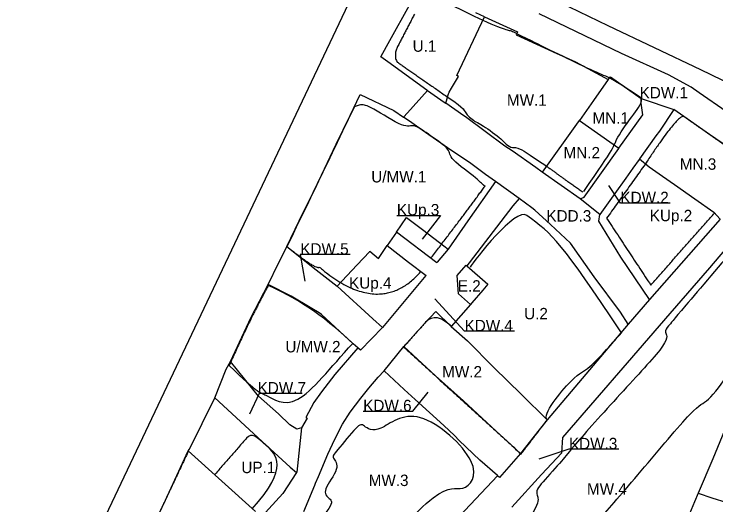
# Model space of a CAD drawing. Extents: x 7424788 to 7425732, y 5549810 to 5550591.
# Drawn here: x 7425037.8 to 7425283.7, y 5550276.4 to 5550448.5 of the extents above; entities that cross this region are included whole.
import ezdxf

# ---------------------------------------------------------------- set-up
doc = ezdxf.new("R2010")
doc.units = 0
for name, color, linetype in [('WIL_granica obszaru objętego planem', 7, 'Continuous'), ('WIL_linia rozgraniczające tereny o różnym przeznaczeniu lub różnych zasadach zagospodarowania', 7, 'Continuous'), ('WIL_linia rozgraniczające tereny o różnym przeznaczeniu lub różnych zasadach zagospodarowania_OPISY', 7, 'Continuous'), ('WIL_nieprzekraczalne linie zabudowy', 7, 'Continuous')]:
    doc.layers.add(name, color=color, linetype=linetype)

msp = doc.modelspace()

# ---------------------------------------------------------------- linework, layer by layer
at = {"layer": 'WIL_granica obszaru objętego planem'}
msp.add_line((7424904.13, 5549923.06), (7425177.26, 5550499.06), dxfattribs=at)
at = {"layer": 'WIL_linia rozgraniczające tereny o różnym przeznaczeniu lub różnych zasadach zagospodarowania'}
for p, q in [((7424904.13, 5549923.06), (7425177.26, 5550499.06)), ((7425207.99, 5550462.87), (7425245.88, 5550444.53)), ((7425168.28, 5550437.16), (7425177.56, 5550453.84)), ((7425192.92, 5550426.96), (7425202.6, 5550447.56)), ((7425202.6, 5550447.56), (7425199.62, 5550448.89)), ((7425202.6, 5550447.56), (7425214.19, 5550442.28)), ((7425250.66, 5550434.71), (7425221.8, 5550448.54)), ((7425245.88, 5550444.53), (7425278.31, 5550429.04)), ((7425214.19, 5550442.28), (7425213.71, 5550441.25)), ((7425213.71, 5550441.25), (7425227.98, 5550434.72)), ((7425166.26, 5550433.54), (7425168.28, 5550437.16)), ((7425168.74, 5550431.75), (7425166.26, 5550433.54)), ((7425227.98, 5550434.72), (7425230.92, 5550433.39)), ((7425230.92, 5550433.39), (7425234.46, 5550431.78)), ((7425267.09, 5550427.17), (7425250.66, 5550434.71)), ((7425182.4, 5550421.84), (7425168.74, 5550431.75)), ((7425234.46, 5550431.78), (7425245.94, 5550425.55)), ((7425278.31, 5550429.04), (7425324.29, 5550406.7)), ((7425191.09, 5550422.52), (7425193.55, 5550426.58)), ((7425193.55, 5550426.58), (7425192.92, 5550426.96)), ((7425245.94, 5550425.55), (7425240.78, 5550418.23)), ((7425245.94, 5550425.55), (7425246.71, 5550426.54)), ((7425246.71, 5550426.54), (7425257.54, 5550418.86)), ((7425275, 5550422.9), (7425267.09, 5550427.17)), ((7425175.64, 5550413.93), (7425182.63, 5550421.68)), ((7425182.63, 5550421.68), (7425182.4, 5550421.84)), ((7425182.63, 5550421.68), (7425188.49, 5550417.61)), ((7425189.93, 5550420.15), (7425190.22, 5550421.08)), ((7425190.22, 5550421.08), (7425191.09, 5550422.52)), ((7425277.85, 5550420.91), (7425275, 5550422.9)), ((7425287.26, 5550414.34), (7425277.85, 5550420.91)), ((7425155.57, 5550412.91), (7425159.06, 5550420.34)), ((7425159.06, 5550420.34), (7425170.83, 5550414.69)), ((7425189.06, 5550417.22), (7425189.93, 5550420.15)), ((7425240.78, 5550418.23), (7425239.94, 5550417.03)), ((7425257.47, 5550417.23), (7425257.54, 5550418.86)), ((7425257.54, 5550418.86), (7425268.97, 5550415.01)), ((7425188.49, 5550417.61), (7425189.06, 5550417.22)), ((7425195.43, 5550412.8), (7425189.06, 5550417.22)), ((7425239.94, 5550417.03), (7425235.87, 5550411.24)), ((7425258.1, 5550413.19), (7425257.47, 5550417.23)), ((7425170.83, 5550414.69), (7425174.21, 5550412.34)), ((7425174.26, 5550412.31), (7425175.64, 5550413.93)), ((7425249.74, 5550401.45), (7425258.1, 5550413.19)), ((7425268.97, 5550415.01), (7425263.91, 5550407.46)), ((7425272.45, 5550412.59), (7425268.97, 5550415.01)), ((7425150.71, 5550402.86), (7425155.57, 5550412.91)), ((7425174.21, 5550412.34), (7425174.26, 5550412.31)), ((7425177.12, 5550410.32), (7425174.26, 5550412.31)), ((7425195.92, 5550412.44), (7425195.43, 5550412.8)), ((7425209.76, 5550402.2), (7425195.92, 5550412.44)), ((7425235.48, 5550410.76), (7425222.82, 5550393.09)), ((7425235.82, 5550411.17), (7425235.48, 5550410.76)), ((7425235.87, 5550411.24), (7425235.82, 5550411.17)), ((7425235.87, 5550411.24), (7425249.74, 5550401.45)), ((7425281.41, 5550406.3), (7425272.45, 5550412.59)), ((7425179.62, 5550408.63), (7425177.12, 5550410.32)), ((7425183.09, 5550406.13), (7425179.62, 5550408.63)), ((7425191.17, 5550400.58), (7425183.09, 5550406.13)), ((7425262.66, 5550405.83), (7425256.92, 5550397.75)), ((7425263.91, 5550407.46), (7425262.66, 5550405.83)), ((7425288.42, 5550401.48), (7425281.41, 5550406.3)), ((7425145.51, 5550392.02), (7425150.71, 5550402.86)), ((7425212.34, 5550400.51), (7425209.76, 5550402.2)), ((7425237.56, 5550384.37), (7425249.69, 5550401.37)), ((7425249.69, 5550401.37), (7425249.74, 5550401.45)), ((7425197.31, 5550396.45), (7425191.17, 5550400.58)), ((7425220.56, 5550394.69), (7425212.34, 5550400.51)), ((7425203.03, 5550392.29), (7425197.31, 5550396.45)), ((7425256.76, 5550397.52), (7425254.59, 5550394.46)), ((7425256.92, 5550397.75), (7425256.76, 5550397.52)), ((7425256.92, 5550397.75), (7425260.32, 5550395)), ((7425222.82, 5550393.09), (7425220.56, 5550394.69)), ((7425254.59, 5550394.46), (7425252.13, 5550390.99)), ((7425260.32, 5550395), (7425265.01, 5550391.69)), ((7425141.19, 5550383.01), (7425145.51, 5550392.02)), ((7425206.42, 5550389.85), (7425203.03, 5550392.29)), ((7425236.11, 5550383.72), (7425222.82, 5550393.09)), ((7425252.13, 5550390.99), (7425248.31, 5550385.61)), ((7425265.01, 5550391.69), (7425269.21, 5550388.74)), ((7425206.42, 5550389.85), (7425196.79, 5550376.03)), ((7425214.71, 5550383.8), (7425206.42, 5550389.85)), ((7425269.21, 5550388.74), (7425276.33, 5550383.73)), ((7425214.71, 5550383.8), (7425212.6, 5550381.24)), ((7425219.17, 5550380.54), (7425214.71, 5550383.8)), ((7425236.11, 5550383.72), (7425237.56, 5550384.37)), ((7425243.07, 5550378.23), (7425236.11, 5550383.72)), ((7425248.31, 5550385.61), (7425243.07, 5550378.23)), ((7425276.33, 5550383.73), (7425283, 5550379.03)), ((7425139.07, 5550378.94), (7425141.19, 5550383.01)), ((7425212.6, 5550381.24), (7425197.25, 5550361.32)), ((7425133.43, 5550367.01), (7425139.07, 5550378.94)), ((7425220.26, 5550379.78), (7425219.17, 5550380.54)), ((7425225.71, 5550374.68), (7425220.26, 5550379.78)), ((7425283, 5550379.03), (7425285.18, 5550376.64)), ((7425171.76, 5550372.04), (7425175.27, 5550377.23)), ((7425175.27, 5550377.23), (7425180.86, 5550372.98)), ((7425242.68, 5550375.86), (7425243.07, 5550378.23)), ((7425285.18, 5550376.64), (7425260.42, 5550348.39)), ((7425196.79, 5550376.03), (7425189.88, 5550366.12)), ((7425232.71, 5550368.14), (7425225.71, 5550374.68)), ((7425249.13, 5550365.42), (7425242.68, 5550375.86)), ((7425171.76, 5550372.04), (7425168.58, 5550367.37)), ((7425185.87, 5550361.32), (7425171.76, 5550372.04)), ((7425180.86, 5550372.98), (7425186.9, 5550368.4)), ((7425128.69, 5550357.51), (7425133.43, 5550367.01)), ((7425133.43, 5550367.01), (7425143.67, 5550358.85)), ((7425165.48, 5550362.78), (7425168.58, 5550367.37)), ((7425168.58, 5550367.37), (7425175.96, 5550361.54)), ((7425186.9, 5550368.4), (7425189.88, 5550366.12)), ((7425241.01, 5550356.38), (7425232.71, 5550368.14)), ((7425281.55, 5550359.6), (7425288.84, 5550368.05)), ((7425157.85, 5550360.43), (7425162.4, 5550365.33)), ((7425162.4, 5550365.33), (7425162.42, 5550365.34)), ((7425162.42, 5550365.34), (7425165.48, 5550362.78)), ((7425189.88, 5550366.12), (7425186.05, 5550361.53)), ((7425250.42, 5550363.33), (7425249.13, 5550365.42)), ((7425175.96, 5550361.54), (7425182.15, 5550356.86)), ((7425186.05, 5550361.53), (7425185.87, 5550361.32)), ((7425260.42, 5550348.39), (7425250.42, 5550363.33)), ((7425150.99, 5550353.08), (7425157.85, 5550360.43)), ((7425193.04, 5550356.91), (7425196.17, 5550360.49)), ((7425196.17, 5550360.49), (7425196.4, 5550360.29)), ((7425197.25, 5550361.32), (7425196.4, 5550360.29)), ((7425196.4, 5550360.29), (7425203.84, 5550353.77)), ((7425267.7, 5550343.56), (7425281.55, 5550359.6)), ((7425126.86, 5550353.73), (7425128.6, 5550357.34)), ((7425128.6, 5550357.34), (7425128.69, 5550357.51)), ((7425143.67, 5550358.85), (7425150.99, 5550353.08)), ((7425182.12, 5550356.82), (7425166.93, 5550338.62)), ((7425182.15, 5550356.86), (7425182.12, 5550356.82)), ((7425193.47, 5550350.41), (7425193.04, 5550356.91)), ((7425250.32, 5550344), (7425241.01, 5550356.38)), ((7425120.75, 5550342.02), (7425126.86, 5550353.73)), ((7425134.94, 5550349.6), (7425126.86, 5550353.73)), ((7425163.52, 5550341.65), (7425150.99, 5550353.08)), ((7425202.09, 5550351.77), (7425198.14, 5550347.25)), ((7425203.84, 5550353.77), (7425202.09, 5550351.77)), ((7425141.58, 5550345.61), (7425134.94, 5550349.6)), ((7425197.69, 5550346.72), (7425193.47, 5550350.41)), ((7425198.14, 5550347.25), (7425197.69, 5550346.72)), ((7425260.42, 5550348.39), (7425252.9, 5550339.81)), ((7425144.66, 5550343.8), (7425141.58, 5550345.61)), ((7425181.86, 5550340.23), (7425185.58, 5550344.28)), ((7425185.58, 5550344.28), (7425190.96, 5550339.03)), ((7425197.69, 5550346.72), (7425190.96, 5550339.03)), ((7425119.22, 5550338.8), (7425120.75, 5550342.02)), ((7425145.46, 5550343.14), (7425144.66, 5550343.8)), ((7425156.59, 5550332.92), (7425145.46, 5550343.14)), ((7425252.9, 5550339.81), (7425250.32, 5550344)), ((7425252.75, 5550326.27), (7425267.7, 5550343.56)), ((7425166.93, 5550338.62), (7425163.52, 5550341.65)), ((7425174.35, 5550332.02), (7425181.86, 5550340.23)), ((7425252.9, 5550339.81), (7425224.56, 5550306.25)), ((7425113.64, 5550326.7), (7425119.22, 5550338.8)), ((7425166.93, 5550338.62), (7425159.18, 5550330.66)), ((7425190.96, 5550339.03), (7425196.62, 5550333.94)), ((7425158.25, 5550331.47), (7425156.59, 5550332.92)), ((7425167.43, 5550323.42), (7425174.35, 5550332.02)), ((7425174.35, 5550332.02), (7425185.48, 5550321.66)), ((7425196.62, 5550333.94), (7425205.84, 5550324.64)), ((7425158.25, 5550331.47), (7425150.17, 5550322.1)), ((7425159.18, 5550330.66), (7425158.25, 5550331.47)), ((7425112.07, 5550324.05), (7425113.64, 5550326.7)), ((7425123.43, 5550314.57), (7425113.64, 5550326.7)), ((7425205.84, 5550324.64), (7425215.55, 5550315.2)), ((7425230.09, 5550300.05), (7425252.75, 5550326.27)), ((7425108.12, 5550313.95), (7425112.07, 5550324.05)), ((7425165.41, 5550321.19), (7425167.43, 5550323.42)), ((7425174.51, 5550316.93), (7425167.43, 5550323.42)), ((7425150.17, 5550322.1), (7425145.52, 5550316.1)), ((7425162.15, 5550317.33), (7425165.41, 5550321.19)), ((7425185.48, 5550321.66), (7425195.21, 5550312.87)), ((7425159.27, 5550313.83), (7425162.15, 5550317.33)), ((7425145.52, 5550316.1), (7425142.81, 5550312.33)), ((7425178.33, 5550313.44), (7425174.51, 5550316.93)), ((7425215.55, 5550315.2), (7425224.56, 5550306.25)), ((7425099.24, 5550296.01), (7425108.12, 5550313.95)), ((7425108.12, 5550313.95), (7425124.71, 5550298.71)), ((7425130.5, 5550308.36), (7425123.43, 5550314.57)), ((7425142.81, 5550312.33), (7425140.04, 5550307.1)), ((7425155.55, 5550308.93), (7425159.27, 5550313.83)), ((7425188.35, 5550304.25), (7425178.33, 5550313.44)), ((7425195.21, 5550312.87), (7425205.05, 5550303.83)), ((7425134.45, 5550304.57), (7425130.5, 5550308.36)), ((7425152.9, 5550304.8), (7425155.55, 5550308.93)), ((7425140.47, 5550306.85), (7425138.53, 5550303.47)), ((7425140.04, 5550307.1), (7425140.47, 5550306.85)), ((7425224.56, 5550306.25), (7425221.76, 5550302.72)), ((7425136.88, 5550302.96), (7425134.45, 5550304.57)), ((7425138.53, 5550303.47), (7425136.84, 5550287.89)), ((7425138.53, 5550303.47), (7425136.88, 5550302.96)), ((7425150.14, 5550299.52), (7425152.9, 5550304.8)), ((7425192.06, 5550300.72), (7425188.35, 5550304.25)), ((7425205.05, 5550303.83), (7425209.68, 5550299.56)), ((7425221.76, 5550302.72), (7425215.19, 5550294.45)), ((7425286.73, 5550302.51), (7425282.57, 5550292.54)), ((7425193.78, 5550299.08), (7425192.06, 5550300.72)), ((7425229.67, 5550294.69), (7425230.09, 5550300.05)), ((7425124.71, 5550298.71), (7425134.5, 5550289.66)), ((7425147.78, 5550294.2), (7425150.14, 5550299.52)), ((7425200.99, 5550292.1), (7425193.78, 5550299.08)), ((7425209.68, 5550299.56), (7425215.19, 5550294.45)), ((7425090.81, 5550278.06), (7425098.81, 5550295.36)), ((7425098.81, 5550295.36), (7425099.24, 5550296.01)), ((7425098.81, 5550295.36), (7425122.45, 5550274.11)), ((7425144.45, 5550286.46), (7425147.78, 5550294.2)), ((7425215.19, 5550294.45), (7425207.92, 5550286.01)), ((7425222.6, 5550287.16), (7425229.67, 5550294.69)), ((7425207.12, 5550286.71), (7425200.99, 5550292.1)), ((7425282.57, 5550292.54), (7425277.49, 5550280.55)), ((7425136.76, 5550287.77), (7425131.92, 5550280.39)), ((7425134.5, 5550289.66), (7425136.76, 5550287.77)), ((7425136.84, 5550287.89), (7425136.76, 5550287.77)), ((7425143.45, 5550284.02), (7425144.45, 5550286.46)), ((7425207.15, 5550286.68), (7425193.88, 5550272.5)), ((7425207.15, 5550286.68), (7425207.12, 5550286.71)), ((7425207.92, 5550286.01), (7425207.15, 5550286.68)), ((7425212.23, 5550275.61), (7425222.6, 5550287.16)), ((7425139.33, 5550274.15), (7425143.17, 5550283.36)), ((7425143.17, 5550283.36), (7425143.45, 5550284.02)), ((7425131.92, 5550280.39), (7425124.63, 5550272.37)), ((7425277.49, 5550280.55), (7425276.2, 5550277.52)), ((7425277.49, 5550280.55), (7425282.27, 5550278.94)), ((7425085.37, 5550266.74), (7425090.81, 5550278.06)), ((7425282.27, 5550278.94), (7425287.49, 5550277.24)), ((7425276.2, 5550277.52), (7425268.06, 5550258.13))]:
    msp.add_line(p, q, dxfattribs=at)
at = {"layer": 'WIL_linia rozgraniczające tereny o różnym przeznaczeniu lub różnych zasadach zagospodarowania_OPISY'}
for points in [[(7425267.64, 5550382.21), (7425250.23, 5550382.21), (7425246.21, 5550388.41)], [(7425171.92, 5550377.92), (7425187.2, 5550377.92), (7425180.73, 5550369.54)], [(7425155.56, 5550364.18), (7425138.09, 5550364.18), (7425139.72, 5550354.93)], [(7425213.08, 5550337.32), (7425195.65, 5550337.32), (7425185.2, 5550348.68)], [(7425138.78, 5550315.5), (7425123.63, 5550315.5), (7425120.3, 5550308.29)], [(7425160.13, 5550309.29), (7425177.57, 5550309.29), (7425182.92, 5550315.91)], [(7425249.66, 5550295.96), (7425232.21, 5550295.96), (7425221.61, 5550292.45)]]:
    msp.add_lwpolyline(points, dxfattribs=at)
at = {"layer": 'WIL_nieprzekraczalne linie zabudowy'}
for points, degree in [([(7425257.76, 5550418.9), (7425246.92, 5550426.31), (7425245.99, 5550425.78), (7425214.11, 5550441.52), (7425211.86, 5550442.72), (7425208.96, 5550443.12), (7425195.85, 5550449.07), (7425186.99, 5550453.7), (7425182.09, 5550455.88)], 3), ([(7425178.1, 5550448.49), (7425171.99, 5550436.77)], 1), ([(7425171.99, 5550436.77), (7425171.41, 5550435.31), (7425171.37, 5550434.23), (7425171.41, 5550433.26), (7425171.53, 5550432.5), (7425172.05, 5550431.69)], 3), ([(7425172.05, 5550431.69), (7425178.37, 5550427.26), (7425189.88, 5550419.3)], 2), ([(7425189.88, 5550419.3), (7425195.94, 5550415.21), (7425195.26, 5550413.81), (7425200.29, 5550410.1), (7425200.94, 5550410.39), (7425209.89, 5550403.69), (7425209.67, 5550403.11), (7425212.73, 5550401.15), (7425213.89, 5550402.53), (7425221.68, 5550396.93), (7425224.5, 5550395.11)], 3), ([(7425237.39, 5550386.36), (7425248.5, 5550402.1), (7425247.45, 5550403.03), (7425254.72, 5550413.35), (7425257.5, 5550416.65), (7425257.76, 5550418.9)], 3), ([(7425156.93, 5550415.88), (7425145.59, 5550392.09), (7425139.01, 5550378.64), (7425133.43, 5550367.01)], 3), ([(7425156.95, 5550415.88), (7425156.93, 5550415.88)], 1), ([(7425202.88, 5550388.06), (7425201.17, 5550389.35), (7425201.48, 5550389.89), (7425189.59, 5550398.24), (7425191.23, 5550400.67), (7425183.66, 5550405.84), (7425177.18, 5550410.5), (7425175.51, 5550407.81), (7425162.12, 5550416.54), (7425159.35, 5550416.83), (7425158.04, 5550416.39), (7425156.94, 5550415.92), (7425156.95, 5550415.88)], 3), ([(7425272.45, 5550412.55), (7425270.76, 5550413.8), (7425259.29, 5550396.41)], 2), ([(7425299.17, 5550393.9), (7425272.45, 5550412.55)], 1), ([(7425259.29, 5550396.41), (7425245.42, 5550376.93)], 1), ([(7425224.5, 5550395.11), (7425231.43, 5550390.01), (7425237.13, 5550386.09)], 2), ([(7425183.7, 5550362.79), (7425194.14, 5550376.3), (7425202.81, 5550388.21)], 2), ([(7425217.46, 5550377.95), (7425213.71, 5550380.94), (7425198.89, 5550362.15), (7425197.57, 5550359.77)], 3), ([(7425198.43, 5550207.48), (7425214.24, 5550223.9), (7425226.81, 5550237.4), (7425222.97, 5550241.17), (7425243.74, 5550265.11), (7425240.43, 5550268.16), (7425240.3, 5550268.42), (7425256.84, 5550287.34), (7425277.61, 5550312.54), (7425279.73, 5550311.22), (7425289.78, 5550323.65), (7425286.52, 5550326.6), (7425303.41, 5550346.01), (7425314.85, 5550359.25), (7425313.06, 5550361.03), (7425321.13, 5550371.48), (7425305.65, 5550384.84), (7425294.14, 5550370.95), (7425269.41, 5550342.11), (7425267.03, 5550339.06), (7425265.3, 5550337.01), (7425268.22, 5550334.57), (7425251.81, 5550317.24), (7425232.23, 5550295.28), (7425230.78, 5550292.96), (7425222.05, 5550283.57), (7425219.8, 5550280.13), (7425223.37, 5550276.56), (7425206.92, 5550256.89)], 3), ([(7425260.86, 5550353.5), (7425283.21, 5550378.73)], 1), ([(7425250.59, 5550336.75), (7425229.56, 5550368.58), (7425226.47, 5550371.39), (7425217.46, 5550377.95)], 3), ([(7425245.42, 5550376.93), (7425260.86, 5550353.5)], 1), ([(7425133.43, 5550367.01), (7425143.88, 5550358.66), (7425144.75, 5550359.82)], 2), ([(7425144.75, 5550359.82), (7425165.92, 5550341.77), (7425180.25, 5550358.16)], 2), ([(7425126.83, 5550353.3), (7425120.64, 5550342), (7425113.17, 5550325.31)], 2), ([(7425156.44, 5550333.08), (7425145.71, 5550343.36), (7425135.26, 5550349.85), (7425126.83, 5550353.3)], 3), ([(7425191.22, 5550339), (7425185.53, 5550344.03), (7425183.28, 5550341.64), (7425181.96, 5550340.45)], 3), ([(7425181.96, 5550340.45), (7425174.29, 5550331.85)], 1), ([(7425224.56, 5550306.19), (7425222.71, 5550308.17), (7425235.8, 5550323.92), (7425237.66, 5550322.2), (7425246.78, 5550332.38), (7425250.59, 5550336.75)], 3), ([(7425113.17, 5550325.31), (7425123.72, 5550314.99), (7425124.91, 5550316.57), (7425135.78, 5550307.87), (7425148.62, 5550324.47), (7425156.44, 5550333.08)], 3), ([(7425174.29, 5550331.85), (7425215.43, 5550294.28)], 1), ([(7425140.2, 5550219.85), (7425146.9, 5550228.14), (7425142.94, 5550232.9), (7425158.81, 5550252.21), (7425188.63, 5550285.42), (7425194.4, 5550279.73), (7425203.66, 5550289.65), (7425178.12, 5550312.94), (7425165.03, 5550300.63), (7425159.87, 5550304.6), (7425158.81, 5550305.13), (7425149.95, 5550294.28), (7425149.02, 5550293.23), (7425152.46, 5550289.65), (7425145.32, 5550281.19), (7425148.49, 5550278.41), (7425150.08, 5550277.09), (7425139.5, 5550264.25), (7425133.28, 5550256.18), (7425120.18, 5550240.31), (7425118.49, 5550238.35)], 3), ([(7425215.43, 5550294.28), (7425224.56, 5550306.19)], 1), ([(7425121.21, 5550275.03), (7425134.5, 5550289.72), (7425124.58, 5550298.69), (7425121.07, 5550301.98), (7425119.26, 5550299.82)], 3), ([(7425119.26, 5550299.82), (7425108.23, 5550287.23)], 1), ([(7425098.84, 5550295.15), (7425085.37, 5550266.65)], 1)]:
    msp.add_open_spline(points, degree=degree, dxfattribs=at)

# ---------------------------------------------------------------- texts
at = {"layer": 'WIL_linia rozgraniczające tereny o różnym przeznaczeniu lub różnych zasadach zagospodarowania_OPISY'}
for s, p in [('U.1', (7425177.45, 5550435.29)), ('KDW.1', (7425256.97, 5550418.94)), ('MW.1', (7425210.48, 5550416.35)), ('MN.1', (7425240.43, 5550410.09)), ('MN.2', (7425230.31, 5550397.91)), ('MN.3', (7425271.04, 5550393.92)), ('U/MW.1', (7425162.95, 5550389.48)), ('KDW.2', (7425250.23, 5550382.21)), ('KUp.3', (7425171.92, 5550377.92)), ('KDD.3', (7425224.29, 5550375.77)), ('KUp.2', (7425260.52, 5550375.89)), ('KDW.5', (7425138.09, 5550364.18)), ('KUp.4', (7425155.18, 5550352.25)), ('E.2', (7425193.27, 5550351.21)), ('U.2', (7425216.5, 5550341.51)), ('KDW.4', (7425195.65, 5550337.32)), ('U/MW.2', (7425132.87, 5550329.91)), ('MW.2', (7425187.79, 5550321.11)), ('KDW.7', (7425123.13, 5550315.5)), ('KDW.6', (7425160.13, 5550309.29)), ('KDW.3', (7425232.21, 5550295.96)), ('UP.1', (7425117.44, 5550287.59)), ('MW.3', (7425162.04, 5550283.06)), ('MW.4', (7425238.52, 5550280.05))]:
    msp.add_text(s, height=4, dxfattribs=at).set_placement(p)

doc.saveas('drawing.dxf')
